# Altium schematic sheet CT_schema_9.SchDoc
size 278 x 170 mm
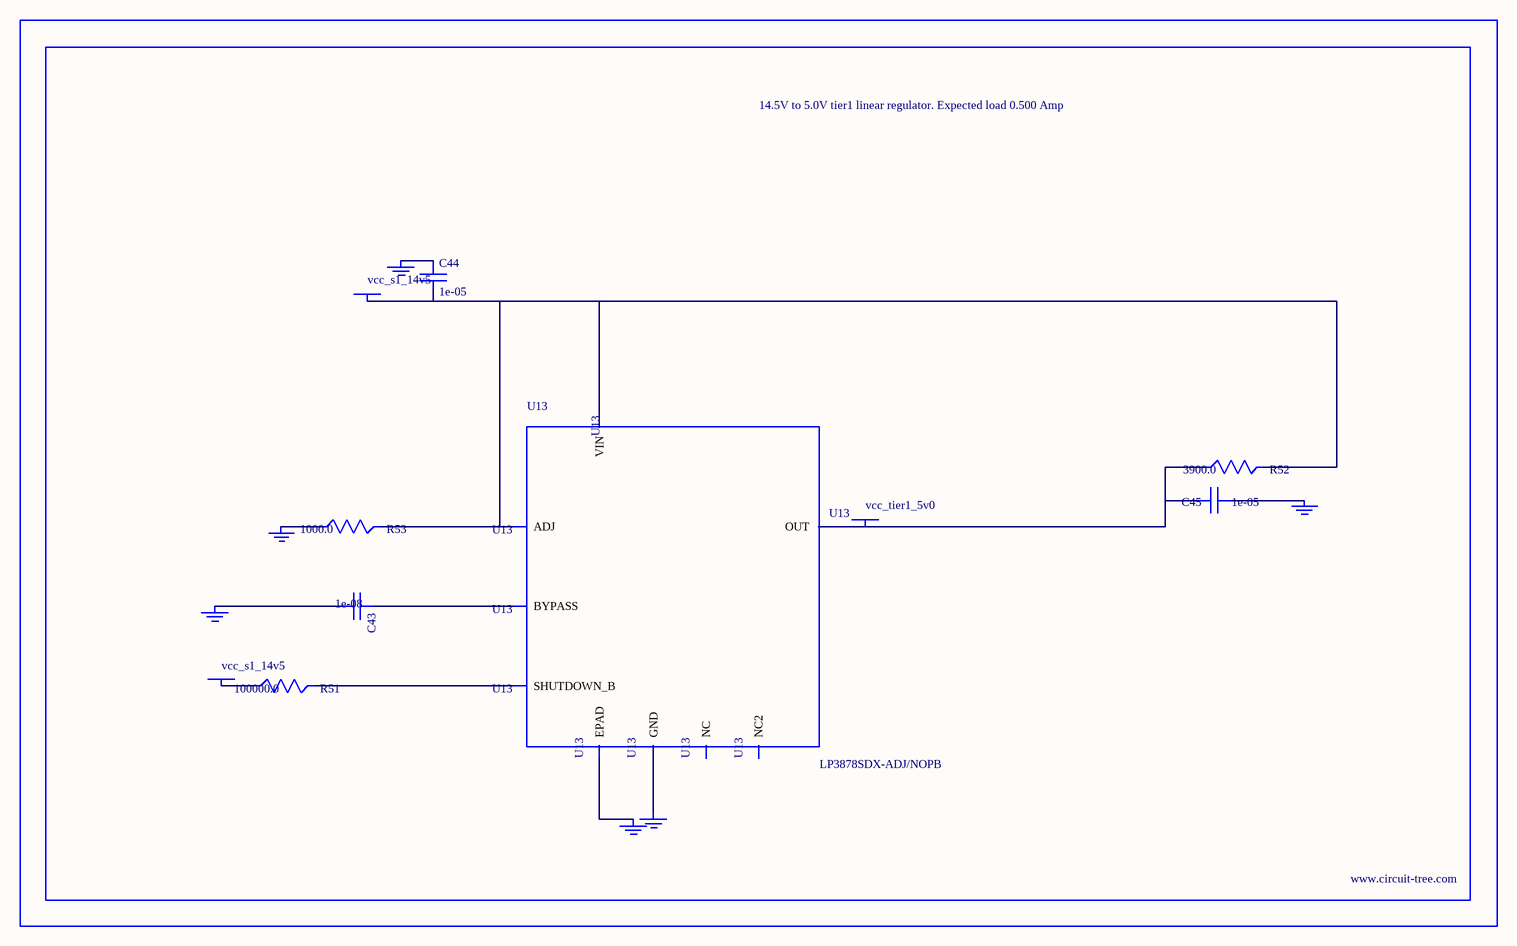
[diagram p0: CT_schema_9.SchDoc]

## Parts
BORDER8  (no value)
C43  1e-08  [C0402]
C44  1e-05  [C1210]
C45  1e-05  [C1210]
GND_INSTANCE_8_0  (no value)
GND_INSTANCE_8_1  (no value)
GND_INSTANCE_8_2  (no value)
GND_INSTANCE_8_3  (no value)
GND_INSTANCE_8_4  (no value)
GND_INSTANCE_8_5  (no value)
POWER_INSTANCE_8_0  vcc_s1_14v5
POWER_INSTANCE_8_1  vcc_s1_14v5
POWER_INSTANCE_8_2  vcc_tier1_5v0
R51  100000.0  [R0603]
R52  3900.0  [R0603]
R53  1000.0  [R0603]
U13  LP3878SDX-ADJ/NOPB  [WSON-8]

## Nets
NetC43_1: C43.1 U13.1(BYPASS)
NetC43_2: C43.2 GND_INSTANCE_8_0.0(GND)
NetC44_1: C44.1 GND_INSTANCE_8_1.0(GND)
NetC44_2: C44.2 POWER_INSTANCE_8_0.0(PWR) R52.2 R53.2 U13.4(VIN) U13.6(ADJ)
NetC45_1: C45.1 GND_INSTANCE_8_2.0(GND)
NetC45_2: C45.2 POWER_INSTANCE_8_2.0(PWR) R52.1 U13.5(OUT)
NetGND_INSTANCE_8_3_0: GND_INSTANCE_8_3.0(GND) R53.1
NetGND_INSTANCE_8_4_0: GND_INSTANCE_8_4.0(GND) U13.PAD(EPAD)
NetGND_INSTANCE_8_5_0: GND_INSTANCE_8_5.0(GND) U13.3(GND)
NetPOWER_INSTANCE_8_1_0: POWER_INSTANCE_8_1.0(PWR) R51.1
NetR51_2: R51.2 U13.8(SHUTDOWN_B)

Not connected (* = marked no-connect by the designer): U13 2(NC) 7(NC2)

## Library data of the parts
BORDER8 = BORDER_PAGE8
C43 = C0402C103K3RAC
C44 = C1210C106K5PACTU
C45 = GRM32DR61E106MA12L
GND_INSTANCE_8_0-GND_INSTANCE_8_5 = GND
POWER_INSTANCE_8_0-POWER_INSTANCE_8_2 = PWR
R51 = RC0603JR-07100KL
R52 = RC0603JR-073K9L
R53 = RC0603JR-071KL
